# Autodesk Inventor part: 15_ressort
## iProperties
Created: 2002-11
Part Number: 15_ressort
Material: Par défaut
Document SubType Name: Modélisation
Designer: FIEVET
Control State: 0
Master: False
Checked Out: False
Shininess: 64.0
Length Units: 11269
Angle Units: 11279
Time Units: 11290
Mass Units: 11283
Length Display Precision: 3
Angle Display Precision: 2
Compacted: True
Density: 0.0
Volumn: 0.0
Area: 0.0
PropertySet Name: Model Information
Author: FIEVET
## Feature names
1. Hélicoïde1
2. Scission1
3. Scission2
